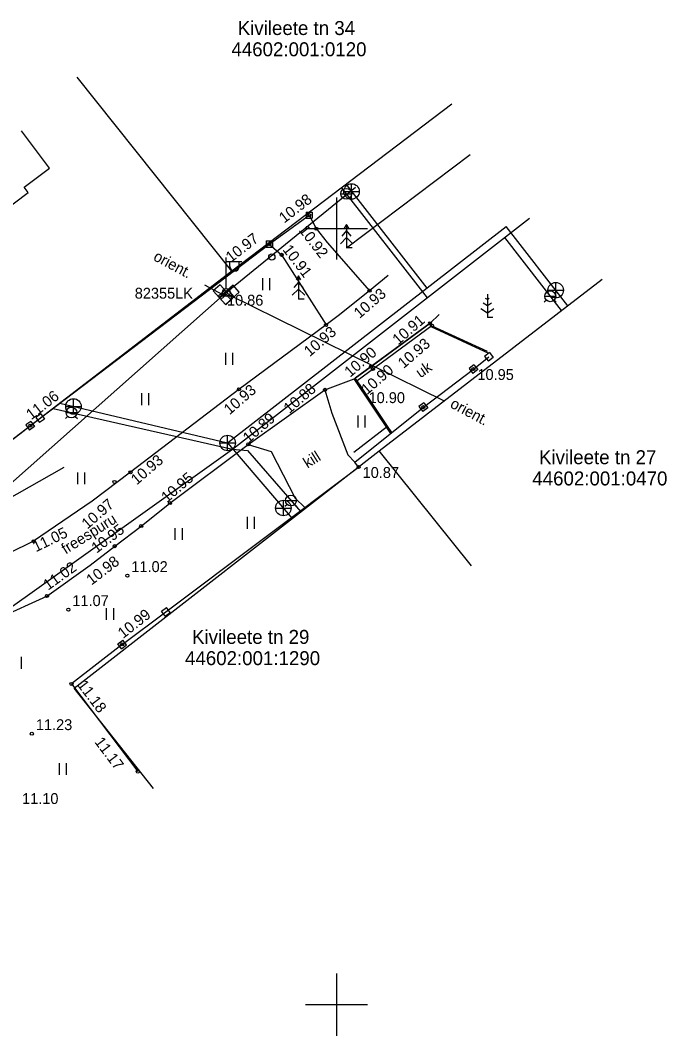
# Model space of a CAD drawing. Extents: x 554198 to 554371, y 6593448 to 6593563.
# Drawn here: x 554329.6 to 554371.3, y 6593498 to 6593563.4 of the extents above; entities that cross this region are included whole.
import ezdxf

# ---------------------------------------------------------------- set-up
doc = ezdxf.new("R2010")
doc.units = 0
for name, color, linetype in [('AED', 7, 'Continuous'), ('ELRAJATISMP', 7, 'Continuous'), ('HALJASTUS', 7, 'Continuous'), ('HOONE', 7, 'Continuous'), ('KKAEV', 7, 'Continuous'), ('KORGUS-EH2000', 7, 'Continuous'), ('KTRASS', 7, 'Continuous'), ('MPKAABEL', 7, 'Continuous'), ('MPOHULIIN', 7, 'Continuous'), ('PIIR', 7, 'Continuous'), ('POST', 7, 'Continuous'), ('PUU', 7, 'Continuous'), ('TEE', 7, 'Continuous'), ('VKAEV', 7, 'Continuous'), ('VORK', 7, 'Continuous'), ('VTRASS', 7, 'Continuous')]:
    doc.layers.add(name, color=color, linetype=linetype)

msp = doc.modelspace()

# ---------------------------------------------------------------- linework, layer by layer
at = {"layer": 'AED'}
for p, q in [((554345.67, 6593548.989), (554348.243, 6593550.852)), ((554348.043, 6593551.052), (554348.043, 6593550.652)), ((554348.043, 6593551.052), (554348.443, 6593551.052)), ((554348.043, 6593550.652), (554348.443, 6593550.652)), ((554348.443, 6593551.052), (554348.443, 6593550.652)), ((554345.47, 6593549.189), (554345.47, 6593548.789)), ((554345.47, 6593549.189), (554345.87, 6593549.189)), ((554345.47, 6593548.789), (554345.87, 6593548.789)), ((554345.87, 6593549.189), (554345.87, 6593548.789)), ((554358.819, 6593540.937), (554359.815, 6593541.719)), ((554359.849, 6593542), (554359.534, 6593541.753)), ((554359.534, 6593541.753), (554359.781, 6593541.438)), ((554360.096, 6593541.685), (554359.781, 6593541.438)), ((554359.849, 6593542), (554360.096, 6593541.685)), ((554355.595, 6593538.486), (554358.819, 6593540.937)), ((554358.853, 6593541.218), (554358.538, 6593540.971)), ((554358.538, 6593540.971), (554358.785, 6593540.656)), ((554359.1, 6593540.903), (554358.785, 6593540.656)), ((554358.853, 6593541.218), (554359.1, 6593540.903)), ((554355.63, 6593538.767), (554355.314, 6593538.521)), ((554355.314, 6593538.521), (554355.56, 6593538.205)), ((554355.876, 6593538.451), (554355.56, 6593538.205)), ((554355.63, 6593538.767), (554355.876, 6593538.451)), ((554330.322, 6593537.572), (554329.999, 6593537.337)), ((554330.278, 6593537.293), (554330.924, 6593537.766)), ((554330.322, 6593537.572), (554330.557, 6593537.249)), ((554330.968, 6593538.045), (554330.645, 6593537.81)), ((554330.645, 6593537.81), (554330.88, 6593537.487)), ((554331.203, 6593537.722), (554330.88, 6593537.487)), ((554330.968, 6593538.045), (554331.203, 6593537.722)), ((554329.999, 6593537.337), (554330.234, 6593537.014)), ((554330.557, 6593537.249), (554330.234, 6593537.014)), ((554336.195, 6593523.205), (554339.008, 6593525.301)), ((554338.728, 6593525.34), (554339.047, 6593525.581)), ((554338.969, 6593525.021), (554338.728, 6593525.34)), ((554338.969, 6593525.021), (554339.288, 6593525.262)), ((554339.288, 6593525.262), (554339.047, 6593525.581)), ((554335.915, 6593523.244), (554336.234, 6593523.485)), ((554336.156, 6593522.925), (554335.915, 6593523.244)), ((554336.156, 6593522.925), (554336.475, 6593523.166)), ((554336.475, 6593523.166), (554336.234, 6593523.485))]:
    msp.add_line(p, q, dxfattribs=at)
for points in [[(554330.924, 6593537.766), (554345.67, 6593548.989)], [(554313.529, 6593544.411), (554315.53, 6593541.932), (554324.135, 6593532.582), (554324.882, 6593533.149), (554330.278, 6593537.293)], [(554339.008, 6593525.301), (554351.424, 6593534.626), (554351.184, 6593534.932), (554355.595, 6593538.486)], [(554336.195, 6593523.205), (554332.931, 6593520.657), (554337.206, 6593515.01)]]:
    msp.add_lwpolyline(points, dxfattribs=at)
at = {"layer": 'ELRAJATISMP'}
for p, q in [((554342.509, 6593546.368), (554342.066, 6593545.968)), ((554342.818, 6593546.025), (554342.374, 6593545.625)), ((554343.34, 6593546.344), (554342.452, 6593545.545)), ((554343.308, 6593545.48), (554342.509, 6593546.368)), ((554342.997, 6593546.035), (554343.396, 6593545.591)), ((554343.739, 6593545.9), (554343.34, 6593546.344)), ((554342.066, 6593545.968), (554342.865, 6593545.08)), ((554342.452, 6593545.545), (554342.851, 6593545.101)), ((554343, 6593545.823), (554342.556, 6593545.423)), ((554342.795, 6593545.854), (554343.194, 6593545.41)), ((554342.851, 6593545.101), (554343.739, 6593545.9)), ((554342.865, 6593545.08), (554343.308, 6593545.48))]:
    msp.add_line(p, q, dxfattribs=at)
at = {"layer": 'HALJASTUS'}
for p, q in [((554345.234, 6593546.784), (554345.234, 6593546.023)), ((554345.689, 6593546.784), (554345.689, 6593546.023)), ((554342.857, 6593541.975), (554342.857, 6593541.214)), ((554343.312, 6593541.975), (554343.312, 6593541.214)), ((554337.44, 6593539.377), (554337.44, 6593538.616)), ((554337.895, 6593539.377), (554337.895, 6593538.616)), ((554351.371, 6593537.947), (554351.371, 6593537.186)), ((554351.826, 6593537.947), (554351.826, 6593537.186)), ((554333.313, 6593534.286), (554333.313, 6593533.525)), ((554333.768, 6593534.286), (554333.768, 6593533.525)), ((554344.239, 6593531.417), (554344.239, 6593530.656)), ((554344.694, 6593531.417), (554344.694, 6593530.656)), ((554339.596, 6593530.698), (554339.596, 6593529.937)), ((554340.051, 6593530.698), (554340.051, 6593529.937)), ((554335.177, 6593525.547), (554335.177, 6593524.786)), ((554335.632, 6593525.547), (554335.632, 6593524.786)), ((554329.683, 6593522.396), (554329.683, 6593521.635)), ((554332.132, 6593515.563), (554332.132, 6593514.801)), ((554332.587, 6593515.563), (554332.587, 6593514.801))]:
    msp.add_line(p, q, dxfattribs=at)
for points in [[(554350.654, 6593548.755), (554358.607, 6593554.757)], [(554351.12, 6593535.594), (554353.285, 6593537.266)], [(554332.43, 6593534.6), (554324.779, 6593530.257), (554320.14, 6593531.245), (554313.27, 6593535.93)]]:
    msp.add_lwpolyline(points, dxfattribs=at)
at = {"layer": 'HOONE'}
msp.add_lwpolyline([(554321.892, 6593549.844), (554323.7, 6593547.45), (554330.15, 6593552.32), (554329.892, 6593552.661), (554331.52, 6593553.89), (554329.712, 6593556.284)], dxfattribs=at)
at = {"layer": 'KKAEV'}
for p, q in [((554350.97, 6593551.88), (554350.97, 6593552.88)), ((554350.47, 6593552.38), (554351.47, 6593552.38)), ((554363.62, 6593546.02), (554364.62, 6593546.02)), ((554364.12, 6593545.52), (554364.12, 6593546.52)), ((554333.06, 6593538.03), (554333.06, 6593539.03)), ((554332.56, 6593538.53), (554333.56, 6593538.53)), ((554342.99, 6593535.68), (554342.99, 6593536.68)), ((554342.49, 6593536.18), (554343.49, 6593536.18)), ((554346.58, 6593531.49), (554346.58, 6593532.49)), ((554346.08, 6593531.99), (554347.08, 6593531.99))]:
    msp.add_line(p, q, dxfattribs=at)
for centre in [(554350.97, 6593552.38), (554364.12, 6593546.02), (554333.06, 6593538.53), (554342.99, 6593536.18), (554346.58, 6593531.99)]:
    msp.add_circle(centre, 0.5, dxfattribs=at)
at = {"layer": 'KORGUS-EH2000'}
for centre in [(554348.243, 6593550.852), (554348.701, 6593549.988), (554345.67, 6593548.989), (554346.465, 6593548.294), (554352.129, 6593545.987), (554342.687, 6593545.724), (554349.33, 6593543.783), (554356.031, 6593543.892), (554356.149, 6593543.731), (554352.231, 6593541.099), (554352.349, 6593540.938), (554358.819, 6593540.937), (554343.716, 6593539.631), (554349.258, 6593539.604), (554355.595, 6593538.486), (554330.278, 6593537.293), (554344.321, 6593536.086), (554336.737, 6593534.292), (554351.424, 6593534.626), (554335.7, 6593533.67), (554339.271, 6593532.306), (554337.42, 6593530.83), (554330.49, 6593529.85), (554335.72, 6593529.53), (554336.53, 6593527.63), (554331.35, 6593526.32), (554332.73, 6593525.44), (554336.195, 6593523.205), (554332.931, 6593520.657), (554330.38, 6593517.45), (554337.206, 6593515.01)]:
    msp.add_circle(centre, 0.1, dxfattribs=at)
at = {"layer": 'KTRASS'}
for points in [[(554350.619, 6593552.832), (554355.815, 6593546.142)], [(554342.99, 6593536.18), (554360.936, 6593550.119)], [(554364.899, 6593545.017), (554360.936, 6593550.119)], [(554332.179, 6593538.739), (554342.99, 6593536.18)], [(554342.99, 6593536.18), (554347.157, 6593531.317)]]:
    msp.add_lwpolyline(points, dxfattribs=at)
at = {"layer": 'MPKAABEL'}
for points in [[(554342.687, 6593545.724), (554341.52, 6593546.349)], [(554343.092, 6593545.72), (554356.934, 6593538.89)]]:
    msp.add_lwpolyline(points, dxfattribs=at)
at = {"layer": 'MPOHULIIN'}
for points in [[(554342.904, 6593545.872), (554351.224, 6593552.648)], [(554314.701, 6593520.885), (554342.904, 6593545.872)]]:
    msp.add_lwpolyline(points, dxfattribs=at)
at = {"layer": 'PIIR'}
for p, q in [((554343.27, 6593547.24), (554333.302, 6593559.747)), ((554357.427, 6593558.012), (554343.27, 6593547.24)), ((554343.27, 6593547.24), (554323.57, 6593532.14)), ((554352.76, 6593535.68), (554367.116, 6593546.722)), ((554333.11, 6593520.38), (554352.76, 6593535.68)), ((554358.707, 6593528.258), (554352.76, 6593535.68)), ((554338.221, 6593513.92), (554333.11, 6593520.38))]:
    msp.add_line(p, q, dxfattribs=at)
at = {"layer": 'POST'}
for p, q in [((554342.904, 6593546.122), (554342.904, 6593548.122)), ((554342.904, 6593547.872), (554343.904, 6593547.872)), ((554343.131, 6593547.551), (554343.131, 6593547.872)), ((554343.743, 6593547.551), (554343.743, 6593547.872))]:
    msp.add_line(p, q, dxfattribs=at)
for centre, radius in [((554345.836, 6593548.153), 0.2), ((554342.904, 6593545.872), 0.25)]:
    msp.add_circle(centre, radius, dxfattribs=at)
msp.add_arc((554343.437, 6593547.551), 0.306, 180, 0, dxfattribs=at)
at = {"layer": 'PUU'}
for p, q in [((554350.654, 6593550.255), (554350.504, 6593550.005)), ((554350.804, 6593550.005), (554350.654, 6593550.255)), ((554350.654, 6593550.255), (554350.654, 6593548.755)), ((554350.654, 6593549.405), (554350.254, 6593549.005)), ((554350.654, 6593549.855), (554350.354, 6593549.505)), ((554350.954, 6593549.505), (554350.654, 6593549.855)), ((554351.054, 6593549.005), (554350.654, 6593549.405)), ((554351.014, 6593548.755), (554350.654, 6593548.755)), ((554347.555, 6593546.939), (554347.405, 6593546.689)), ((554347.705, 6593546.689), (554347.555, 6593546.939)), ((554347.555, 6593546.939), (554347.555, 6593545.439)), ((554347.555, 6593546.089), (554347.155, 6593545.689)), ((554347.555, 6593546.539), (554347.255, 6593546.189)), ((554347.855, 6593546.189), (554347.555, 6593546.539)), ((554347.955, 6593545.689), (554347.555, 6593546.089)), ((554347.915, 6593545.439), (554347.555, 6593545.439)), ((554359.72, 6593545.41), (554359.596, 6593545.493)), ((554359.72, 6593545.76), (554359.72, 6593544.26)), ((554359.845, 6593545.493), (554359.72, 6593545.41)), ((554359.296, 6593544.849), (554359.72, 6593544.567)), ((554359.72, 6593545.01), (554359.454, 6593545.188)), ((554359.987, 6593545.188), (554359.72, 6593545.01)), ((554359.72, 6593544.567), (554360.145, 6593544.849)), ((554360.08, 6593544.26), (554359.72, 6593544.26))]:
    msp.add_line(p, q, dxfattribs=at)
at = {"layer": 'TEE'}
for points in [[(554348.243, 6593550.852), (554348.701, 6593549.988), (554349.41, 6593549.097), (554352.129, 6593545.987)], [(554345.67, 6593548.989), (554346.465, 6593548.294), (554347.152, 6593547.229), (554349.33, 6593543.783)], [(554353.336, 6593546.96), (554352.129, 6593545.987), (554350.115, 6593544.363), (554349.33, 6593543.783), (554343.716, 6593539.631), (554336.737, 6593534.292), (554334.27, 6593532.44), (554330.49, 6593529.85), (554327.24, 6593528.27)], [(554328.21, 6593524.9), (554331.35, 6593526.32), (554334.14, 6593528.31), (554335.72, 6593529.53), (554337.42, 6593530.83), (554339.271, 6593532.306), (554344.321, 6593536.086), (554349.258, 6593539.604), (554351.147, 6593540.307), (554351.214, 6593540.352), (554352.231, 6593541.099), (554356.031, 6593543.892), (554356.621, 6593544.449)], [(554356.031, 6593543.892), (554351.214, 6593540.352)], [(554356.149, 6593543.731), (554351.325, 6593540.186)], [(554356.149, 6593543.731), (554356.031, 6593543.892)], [(554356.075, 6593543.677), (554359.8, 6593541.961)], [(554356.149, 6593543.731), (554359.705, 6593542.093)], [(554351.147, 6593540.307), (554351.214, 6593540.352)], [(554353.502, 6593536.799), (554351.147, 6593540.307)], [(554353.564, 6593536.85), (554353.285, 6593537.266), (554351.519, 6593539.897), (554351.214, 6593540.352)], [(554349.258, 6593539.604), (554349.695, 6593538.108), (554350.741, 6593535.419), (554351.184, 6593534.932)], [(554344.321, 6593536.086), (554345.789, 6593535.622), (554347.341, 6593532.624), (554347.956, 6593532.021)]]:
    msp.add_lwpolyline(points, dxfattribs=at)
at = {"layer": 'VKAEV'}
for p, q in [((554350.383, 6593551.983), (554350.243, 6593551.843)), ((554350.28, 6593552.23), (554350.98, 6593552.23)), ((554350.877, 6593551.983), (554351.017, 6593551.843)), ((554363.523, 6593545.383), (554363.383, 6593545.243)), ((554363.42, 6593545.63), (554364.12, 6593545.63)), ((554364.017, 6593545.383), (554364.157, 6593545.243)), ((554332.683, 6593537.893), (554332.543, 6593537.753)), ((554332.58, 6593538.14), (554333.28, 6593538.14)), ((554333.177, 6593537.893), (554333.317, 6593537.753)), ((554346.72, 6593532.47), (554347.42, 6593532.47)), ((554346.823, 6593532.223), (554346.683, 6593532.083)), ((554347.317, 6593532.223), (554347.457, 6593532.083))]:
    msp.add_line(p, q, dxfattribs=at)
for centre in [(554350.63, 6593552.23), (554363.77, 6593545.63), (554332.93, 6593538.14), (554347.07, 6593532.47)]:
    msp.add_circle(centre, 0.35, dxfattribs=at)
at = {"layer": 'VORK'}
for p, q in [((554350, 6593552), (554350, 6593548)), ((554348, 6593550), (554352, 6593550)), ((554350, 6593502), (554350, 6593498)), ((554348, 6593500), (554352, 6593500))]:
    msp.add_line(p, q, dxfattribs=at)
at = {"layer": 'VTRASS'}
for points in [[(554350.332, 6593552.614), (554355.833, 6593545.523)], [(554320.351, 6593519.114), (554321.687, 6593520.357), (554343.297, 6593535.785), (554362.436, 6593550.651)], [(554364.49, 6593544.703), (554360.835, 6593549.408)], [(554331.748, 6593538.408), (554343.297, 6593535.785)], [(554343.297, 6593535.785), (554344.262, 6593535.686), (554347.704, 6593531.743)]]:
    msp.add_lwpolyline(points, dxfattribs=at)

# ---------------------------------------------------------------- texts
at = {"layer": 'ELRAJATISMP'}
msp.add_text('82355LK', height=0.7, dxfattribs=at).set_placement((554337.008, 6593545.474))
at = {"layer": 'KORGUS-EH2000'}
for s, rotation, p in [(' 10.98 ', 37.62896, (554346.426, 6593550.145)), (' 10.92 ', 307.52646, (554347.382, 6593550.083)), (' 10.97 ', 37.62896, (554342.995, 6593547.616)), (' 10.91 ', 307.52646, (554346.34, 6593548.829)), (' 10.93 ', 40.70014, (554351.286, 6593543.992)), (' 10.91 ', 40.70014, (554353.779, 6593542.285)), (' 10.93 ', 40.70014, (554348.076, 6593541.531)), (' 10.93 ', 40.70014, (554354.125, 6593540.77)), (' 10.90 ', 40.70014, (554350.683, 6593540.204)), (' 10.90 ', 40.70014, (554351.766, 6593539.078)), (' 11.06 ', 37.52341, (554330.136, 6593537.478)), (' 10.93 ', 40.70014, (554342.917, 6593537.79)), (' 10.88 ', 40.70014, (554346.764, 6593537.862)), (' 10.89 ', 40.70014, (554344.14, 6593535.961)), (' 10.93 ', 40.70014, (554336.933, 6593533.269)), (' 10.95 ', 40.70014, (554338.885, 6593532.132)), (' 10.97 ', 40.70014, (554333.757, 6593530.424)), (' 10.95 ', 37.40536, (554334.342, 6593528.885)), (' 11.05 ', 25.92688, (554330.411, 6593529.022)), (' 11.02 ', 35.49881, (554331.215, 6593526.51)), (' 10.98 ', 37.40536, (554334.015, 6593526.829)), (' 10.99 ', 37.97692, (554336.051, 6593523.389)), (' 11.18 ', 307.12715, (554333.117, 6593520.798)), (' 11.17 ', 307.12715, (554334.226, 6593517.122))]:
    msp.add_text(s, height=0.7, rotation=rotation, dxfattribs=at).set_placement(p)
for s, p in [(' 10.86 ', (554342.687, 6593545.024)), (' 10.95 ', (554358.819, 6593540.237)), (' 10.90 ', (554351.808, 6593538.747)), (' 10.87 ', (554351.424, 6593533.926)), (' 11.02 ', (554336.53, 6593527.863)), (' 11.07 ', (554332.73, 6593525.673)), (' 11.23 ', (554330.38, 6593517.683)), (' 11.10 ', (554329.49, 6593512.923))]:
    msp.add_text(s, height=0.7, dxfattribs=at).set_placement(p)
at = {"layer": 'MPKAABEL'}
for p in [(554338.149, 6593547.985), (554357.264, 6593538.501)]:
    msp.add_text('orient.', height=0.7, rotation=331.81149, dxfattribs=at).set_placement(p)
at = {"layer": 'PIIR'}
for s, p in [('Kivileete tn 34', (554343.64, 6593562.456)), ('44602:001:0120', (554343.233, 6593561.087)), ('Kivileete tn 27', (554363.043, 6593534.812)), ('44602:001:0470', (554362.615, 6593533.444)), ('Kivileete tn 29', (554340.696, 6593523.237)), ('44602:001:1290', (554340.246, 6593521.868))]:
    msp.add_text(s, height=0.9, dxfattribs=at).set_placement(p)
at = {"layer": 'TEE'}
for s, rotation, p in [('uk', 34.85796, (554355.409, 6593540.336)), ('kill', 32.113, (554348.132, 6593534.527)), ('freespuru', 32.113, (554332.561, 6593528.989))]:
    msp.add_text(s, height=0.7, rotation=rotation, dxfattribs=at).set_placement(p)

doc.saveas('drawing.dxf')
